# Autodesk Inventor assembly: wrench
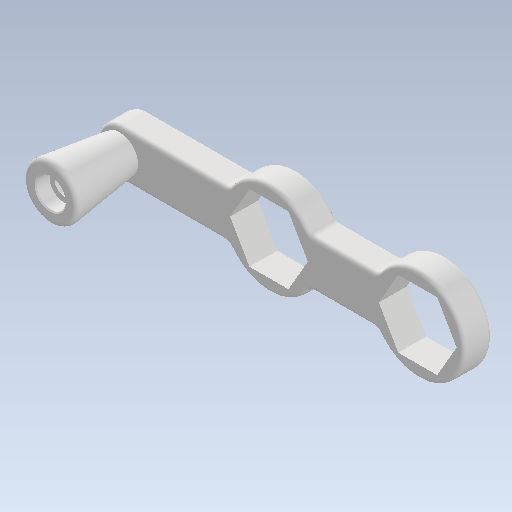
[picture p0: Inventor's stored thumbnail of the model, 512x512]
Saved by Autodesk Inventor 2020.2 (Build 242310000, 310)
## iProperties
Created: 2020-01
Part Number: wrench
Document SubType Name: Assembly
Designer: Patrick Everitt
Author: Patrick Everitt
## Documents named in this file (3)
- C:\Users\Patrick Everitt\Documents\Inventor\Fire_Vise\wrench.iam
- C:\Users\Patrick Everitt\Documents\Inventor\Fire_Vise\Handle.ipt
- C:\Users\Patrick Everitt\Documents\Inventor\Fire_Vise\Knob.ipt
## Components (2 placed, 2 different names)
1. Handle:1 — Mate:1, Mate:2
2. Knob:1 — Mate:1, Mate:2
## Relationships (2: Mate 2)
- Mate:1: Handle:1 ↔ Knob:1
- Mate:2: Handle:1 ↔ Knob:1
